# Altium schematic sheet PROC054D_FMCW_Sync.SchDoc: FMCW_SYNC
size 558 x 431 mm; Date: Not shown in title block; ApprovedBy: Not shown in title block; CheckedBy: Not shown in title block; Author: Not shown in title block; CompanyName: Not shown in title block; DrawnBy: a0271760; Engineer: Not shown in title block; Organization: Not shown in title block; Address1: Not shown in title block; Address2: Not shown in title block; Address3: Not shown in title block; Address4: Not shown in title block; DocumentNumber: 14; Revision: Use project pAWRameter SCH_Rev; SheetNumber: 14; SheetTotal: 19; PageSetup: Record=PageOptions¦CenterHorizontal=True¦CenterVertical=True¦PrintScale=1.00¦XCorrection=1.00¦YCorrection=1.00¦PrintKind=0¦BorderSize=5000000¦LeftOffset=0¦BottomOffset=0¦Orientation=2¦PaperLength=1000¦PaperWidth=1000¦Scale=100¦PaperSource=15¦PrintQuality=600¦MediaType=1¦DitherType=10¦PaperKind=Letter¦PrintScaleMode=1
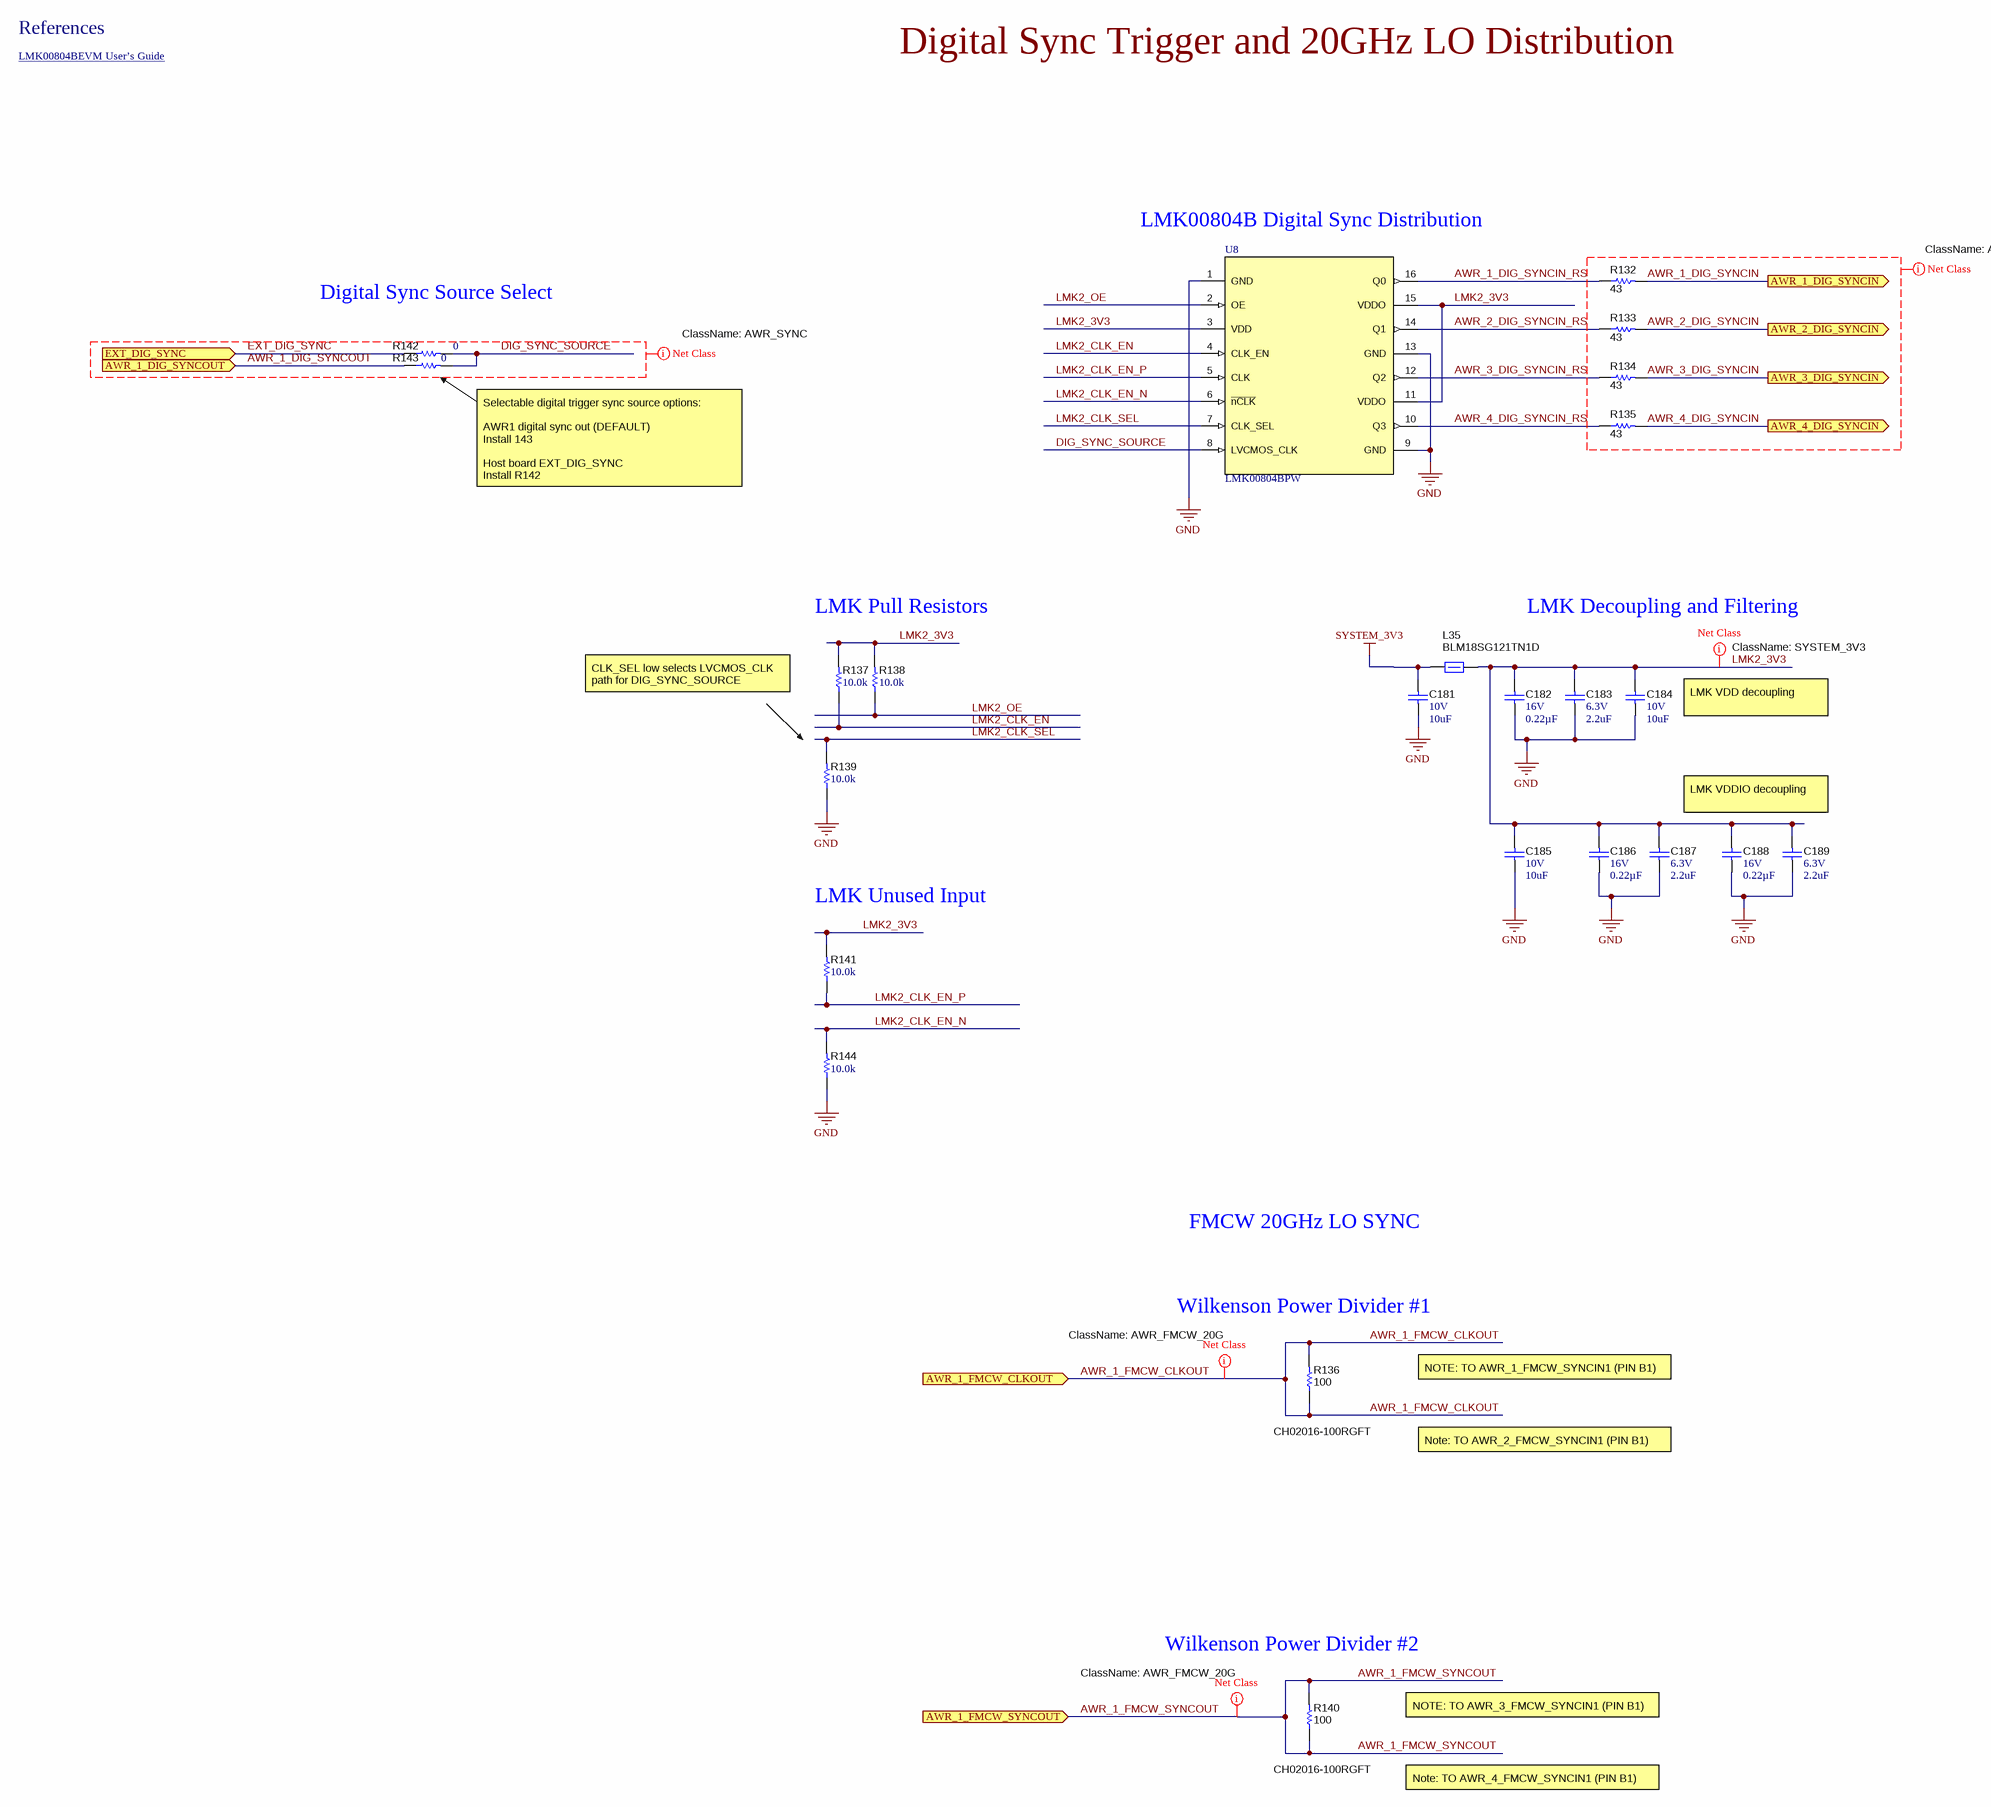
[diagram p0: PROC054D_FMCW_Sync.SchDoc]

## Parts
C181  VDC_V: 10V  ValueDisplayed: 10uF  [0805_HV]  (hidden comment: GCM21BR71A106KE22L)
C182  VDC_V: 16V  ValueDisplayed: 0.22µF  [0402]  (hidden comment: GCM155R71C224KE02D)
C183  VDC_V: 6.3V  ValueDisplayed: 2.2uF  [0603]  (hidden comment: GCM188R70J225KE22D)
C184  VDC_V: 10V  ValueDisplayed: 10uF  [0805_HV]  (hidden comment: GCM21BR71A106KE22L)
C185  VDC_V: 10V  ValueDisplayed: 10uF  [0805_HV]  (hidden comment: GCM21BR71A106KE22L)
C186  VDC_V: 16V  ValueDisplayed: 0.22µF  [0402]  (hidden comment: GCM155R71C224KE02D)
C187  VDC_V: 6.3V  ValueDisplayed: 2.2uF  [0603]  (hidden comment: GCM188R70J225KE22D)
C188  VDC_V: 16V  ValueDisplayed: 0.22µF  [0402]  (hidden comment: GCM155R71C224KE02D)
C189  VDC_V: 6.3V  ValueDisplayed: 2.2uF  [0603]  (hidden comment: GCM188R70J225KE22D)
L35  BLM18SG121TN1D  [0603]
R132  ValueDisplayed: 43  [0402]  (hidden comment: CRCW040243R0JNED)
R133  ValueDisplayed: 43  [0402]  (hidden comment: CRCW040243R0JNED)
R134  ValueDisplayed: 43  [0402]  (hidden comment: CRCW040243R0JNED)
R135  ValueDisplayed: 43  [0402]  (hidden comment: CRCW040243R0JNED)
R136  ValueDisplayed: 100  [02016]  (hidden comment: CH02016-100RGFT)
R137  ValueDisplayed: 10.0k  [0402]  (hidden comment: CRCW040210K0FKED)
R138  ValueDisplayed: 10.0k  [0402]  (hidden comment: CRCW040210K0FKED)
R139  ValueDisplayed: 10.0k  [0402]  (hidden comment: CRCW040210K0FKED)
R140  ValueDisplayed: 100  [02016]  (hidden comment: CH02016-100RGFT)
R141  ValueDisplayed: 10.0k  [0402]  (hidden comment: CRCW040210K0FKED)
R142  ValueDisplayed: 0  [0402]  (hidden comment: ERJ-2GE0R00X)
R143  ValueDisplayed: 0  [0402]  (hidden comment: ERJ-2GE0R00X)
R144  ValueDisplayed: 10.0k  [0402]  (hidden comment: CRCW040210K0FKED)
U8  LMK00804BPW  [PW0016A_N]

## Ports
AWR_1_DIG_SYNCIN (out), AWR_1_DIG_SYNCOUT (in), AWR_1_FMCW_CLKOUT (in), AWR_1_FMCW_SYNCOUT (in), AWR_2_DIG_SYNCIN (out), AWR_3_DIG_SYNCIN (out), AWR_4_DIG_SYNCIN (out), EXT_DIG_SYNC (in)

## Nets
GND: C181.2 C182.2 C183.1 C184.2 C185.2 C186.2 C187.1 C188.2 C189.1 R139.1 R144.1 U8.1(GND) U8.9(GND) U8.13(GND)
SYSTEM_3V3: C181.1 L35.1
AWR_1_DIG_SYNCIN: R132.2 ; port AWR_1_DIG_SYNCIN
AWR_1_DIG_SYNCIN_RS: R132.1 U8.16(Q0)
AWR_1_DIG_SYNCOUT: R143.1 ; port AWR_1_DIG_SYNCOUT
AWR_1_FMCW_CLKOUT: R136.1 R136.2 ; port AWR_1_FMCW_CLKOUT
AWR_1_FMCW_SYNCOUT: R140.1 R140.2 ; port AWR_1_FMCW_SYNCOUT
AWR_2_DIG_SYNCIN: R133.2 ; port AWR_2_DIG_SYNCIN
AWR_2_DIG_SYNCIN_RS: R133.1 U8.14(Q1)
AWR_3_DIG_SYNCIN: R134.2 ; port AWR_3_DIG_SYNCIN
AWR_3_DIG_SYNCIN_RS: R134.1 U8.12(Q2)
AWR_4_DIG_SYNCIN: R135.2 ; port AWR_4_DIG_SYNCIN
AWR_4_DIG_SYNCIN_RS: R135.1 U8.10(Q3)
DIG_SYNC_SOURCE: R142.2 R143.2 U8.8(LVCMOS_CLK)
EXT_DIG_SYNC: R142.1 ; port EXT_DIG_SYNC
LMK2_3V3: C182.1 C183.2 C184.1 C185.1 C186.1 C187.2 C188.1 C189.2 L35.2 R137.2 R138.2 R141.2 U8.3(VDD) U8.11(VDDO) U8.15(VDDO)
LMK2_CLK_EN: R137.1 U8.4(CLK_EN)
LMK2_CLK_EN_N: R144.2 U8.6(~{nCLK})
LMK2_CLK_EN_P: R141.1 U8.5(CLK)
LMK2_CLK_SEL: R139.2 U8.7(CLK_SEL)
LMK2_OE: R138.1 U8.2(OE)

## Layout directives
net class SYSTEM_3V3: LMK2_3V3
net class AWR_FMCW_20G: AWR_1_FMCW_CLKOUT, AWR_1_FMCW_SYNCOUT
net class AWR_SYNC: AWR_1_DIG_SYNCIN, AWR_1_DIG_SYNCOUT, AWR_2_DIG_SYNCIN, AWR_3_DIG_SYNCIN, AWR_4_DIG_SYNCIN, DIG_SYNC_SOURCE, EXT_DIG_SYNC

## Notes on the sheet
- References
- LMK00804BEVM User’s Guide <http://www.ti.com/lit/ug/snou129/snou129.pdf>
- Digital Sync Trigger and 20GHz LO Distribution
- LMK00804B Digital Sync Distribution
- Digital Sync Source Select
- Selectable digital trigger sync source options:
  AWR1 digital sync out (DEFAULT)
  Install 143
  Host board EXT_DIG_SYNC
  Install R142
- LMK Pull Resistors
- LMK Decoupling and Filtering
- CLK_SEL low selects LVCMOS_CLK path for DIG_SYNC_SOURCE
- LMK VDD decoupling
- LMK VDDIO decoupling
- LMK Unused Input
- FMCW 20GHz LO SYNC
- Wilkenson Power Divider #1
- NOTE: TO AWR_1_FMCW_SYNCIN1 (PIN B1)
- Note: TO AWR_2_FMCW_SYNCIN1 (PIN B1)
- Wilkenson Power Divider #2
- NOTE: TO AWR_3_FMCW_SYNCIN1 (PIN B1)
- Note: TO AWR_4_FMCW_SYNCIN1 (PIN B1)

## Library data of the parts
C181 C184 C185 = CMP-0008017-2: CAP, CERM, 10 uF, 10 V, +/- 10%, X7R, 0805; Manufacturer: MuRata; TaMin_C: -55°C; Polarized: N; SizeAreaWB_mm2: 6.75; Value1: Unknown; U/M: EA; Value: 10uF; TaMax_C: 125°C; SizeZ_mm: 1.45; SizeX_mm: 2; SizeY_mm: 1.25; Cap_Case: 0805; SizeArea_mm2: 2.5; CompType: Capacitor; Cap_F: 10µF; AEC Category: Q200
C182 C186 C188 = CMP-0078265-1: CAP, CERM, 0.22 µF, 16 V,+/- 10%, X7R, AEC-Q200 Grade 1, 0402; Manufacturer: MuRata; TaMin_C: -55°C; Polarized: N; SizeAreaWB_mm2: 3; U/M: EA; Value: 0.22uF; TaMax_C: 125°C; SizeZ_mm: 0.6; SizeX_mm: 1; SizeY_mm: 0.5; CompType: Capacitor; AEC Qualified: Y; Cap_F: 220nF; AEC Category: Q200
C183 C187 C189 = CMP-0007134-5: CAP, CERM, 2.2 uF, 6.3 V, +/- 10%, X7R, AEC-Q200 Grade 1, 0603; Manufacturer: MuRata; TaMin_C: -55°C; Polarized: N; SizeAreaWB_mm2: 4.68; Value1: Unknown; U/M: EA; Value: 2.2uF; TaMax_C: 125°C; SizeZ_mm: 1; SizeX_mm: 1.6; SizeY_mm: 0.8; SizeArea_mm2: 1.28; AEC Qualified: Y; Cap_F: 2.2µF; AEC Category: Q200
L35 = CMP-0003352-2: Ferrite Bead, 120 ohm @ 100 MHz, 3 A, 0603; Manufacturer: MuRata; ZTyp@100MHz_Ohm: 120; SizeAreaWB_mm2: 4.68; DCR_ohm: 0.025; Value1: 0.025 ohm; Value: 120 ohm; Imax_A: 3A; SizeZ_mm: 1; SizeX_mm: 1.6; SizeY_mm: 0.8; SizeArea_mm2: 1.28
R132-R135 = CMP-0026932-3: RES, 43, 5%, 0.063 W, AEC-Q200 Grade 0, 0402; Manufacturer: Vishay-Dale; Power_W: 63mW; TempCo: 200 ppm/C; Value_Code: 43R0; Value: 43; EIA_Code: E24; SizeX_mm: 1; SizeY_mm: 0.5; SizeZ_mm: 0.6; Value2: 0.063W; AEC Qualified: Y; VDC_V: 50V; AEC Category: Q200; AEC Grade: 0
R136 = CMP-0083872-1: RES, 100, 2%, 0.03 W, 02016; Manufacturer: Vishay-Semiconductor; Tolerance_%: 5%; Value_Code: 100R; SizeAreaWB_mm2: 2.0572; SizeArea_mm2: 0.1872; AEC Qualified: N; AEC Category: Q200; Value: 100; SizeZ_mm: 0.547; EIA_Code: E24; TempCo: 100 ppm/C; Power_W: 30mW; VDC_V: 30V; SizeY_mm: 0.39; Value2: 0.03W; SizeX_mm: 0.48
R137-R139 R141 R144 = CMP-0025958-3: RES, 10.0 k, 1%, 0.063 W, AEC-Q200 Grade 0, 0402; Manufacturer: Vishay-Dale; Power_W: 63mW; TempCo: 100 ppm/C; Value_Code: 10k0; Value: 10.0k; EIA_Code: E96; Res_ohm: 10k; SizeX_mm: 1; SizeY_mm: 0.5; SizeZ_mm: 0.6; Value2: 0.063W; AEC Qualified: Y; VDC_V: 50V; AEC Category: Q200; AEC Grade: 0
R140 = CMP-0083872-1: RES, 100, 2%, 0.03 W, 02016; Manufacturer: Vishay-Semiconductor; Value_Code: 100R; SizeAreaWB_mm2: 2.0572; SizeArea_mm2: 0.1872; AEC Qualified: N; AEC Category: Q200; Value: 100; SizeZ_mm: 0.547; EIA_Code: E24; TempCo: 100 ppm/C; Power_W: 30mW; VDC_V: 30V; SizeY_mm: 0.39; Value2: 0.03W; Value1: 5%; SizeX_mm: 0.48
R142 = CMP-0026992-3: RES, 0, 5%, 0.1 W, AEC-Q200 Grade 0, 0402; Manufacturer: Panasonic; Power_W: 100mW; TempCo: 600 ppm/C; Value_Code: 0000; Value: 0; EIA_Code: E24; SizeX_mm: 1; SizeY_mm: 0.5; SizeZ_mm: 0.6; Value2: 0.1W; CompType: Resistor; AEC Qualified: Y; VDC_V: 50V; AEC Category: Q200; SizeAreaWB_mm2: 3
R143 = CMP-0026992-3: RES, 0, 5%, 0.1 W, AEC-Q200 Grade 0, 0402; Manufacturer: Panasonic; Power_W: 100mW; TempCo: 600 ppm/C; Value_Code: 0000; Value: 0; EIA_Code: E24; SizeX_mm: 1; SizeY_mm: 0.5; SizeZ_mm: 0.6; Value2: 0.1W; AEC Qualified: Y; VDC_V: 50V; AEC Category: Q200; SizeAreaWB_mm2: 3
U8 = CMP-0065663-1: Low Skew, 1-to-4 Multiplexed Differential/LVCMOS-to-LVCMOS/TTL Fanout Buffer, PW0016A (TSSOP-16); Alternate Manufacturer: Texas Instruments; Green_Lifecycle: Active; SizeAreaWB_mm2: 58.8; Green_REACh: Passed; U/M: EA; SizeZ_mm: 1.2; SizeX_mm: 6.4; SizeY_mm: 5.0; SizeArea_mm2: 32.0; CompType: IC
